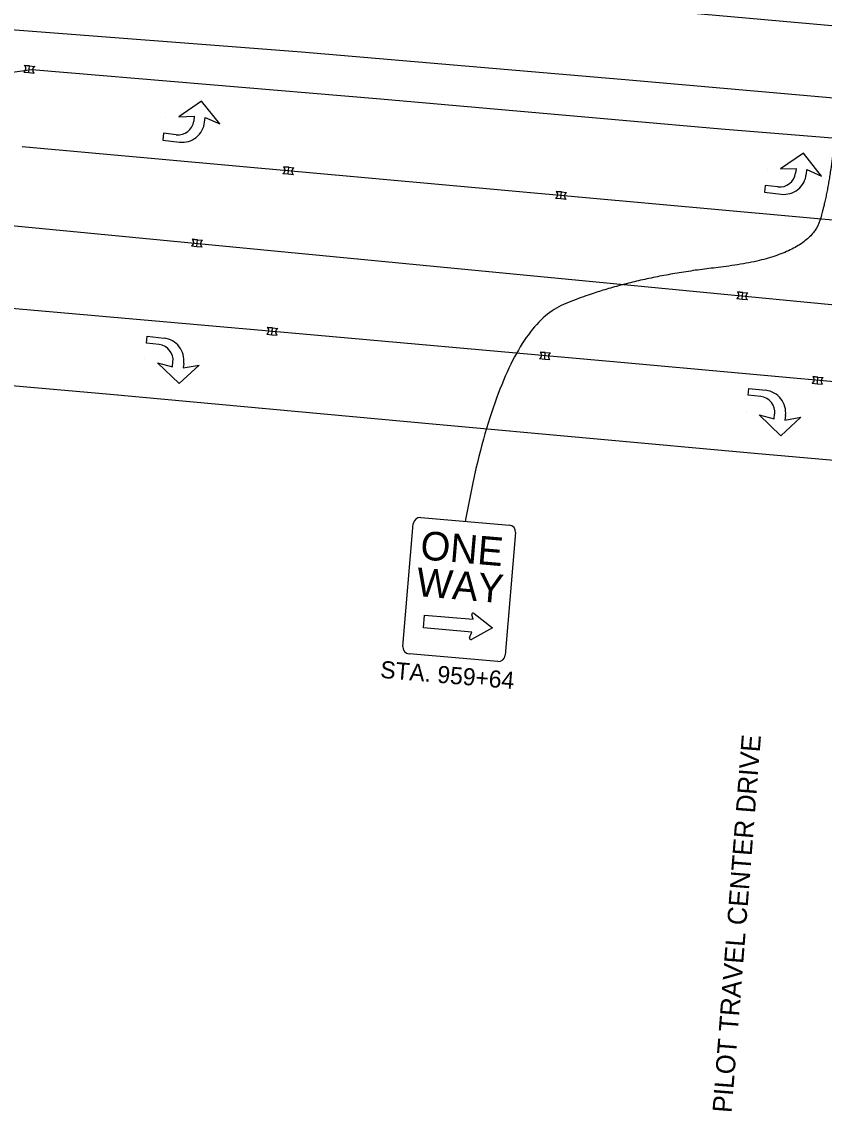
# Model space of a CAD drawing. Extents: x 1847379 to 1850904, y 217032 to 220169.
# Drawn here: x 1849979.4 to 1850096.6, y 218621.4 to 218780.5 of the extents above; entities that cross this region are included whole.
import ezdxf

# ---------------------------------------------------------------- set-up
doc = ezdxf.new("R2010")
doc.units = 0
for name, color, linetype in [('PM_P_Cells', 7, 'Continuous'), ('PM_P_Channelizing_Line', 7, 'Continuous'), ('PM_P_CL_Double_Solid', 7, 'Continuous'), ('PM_P_Edge_Line', 7, 'Continuous'), ('PM_P_Lane_Line', 7, 'Continuous'), ('SN_X_Public', 7, 'Continuous'), ('SN_X_Text', 7, 'Continuous')]:
    doc.layers.add(name, color=color, linetype=linetype)

msp = doc.modelspace()

# ---------------------------------------------------------------- linework, layer by layer
at = {"layer": 'PM_P_Cells'}
for p, q in [((1849980.55, 218774.09), (1849979.78, 218774.16)), ((1849979.78, 218774.16), (1849980.55, 218774.09)), ((1849980.46, 218773.11), (1849980.55, 218774.09)), ((1849980.55, 218774.09), (1849981.31, 218774.02)), ((1849979.69, 218773.18), (1849980.46, 218773.11)), ((1849979.69, 218773.18), (1849980.46, 218773.11)), ((1849980.46, 218773.11), (1849981.23, 218773.04)), ((1850005.68, 218768.96), (1850002.35, 218766.67)), ((1850008.34, 218765.62), (1850005.68, 218768.96)), ((1850000.4, 218766.57), (1850000.4, 218766.57)), ((1850002.35, 218766.67), (1850004.61, 218766.74)), ((1850004.61, 218766.74), (1850004.53, 218766.04)), ((1850006.12, 218765.88), (1850006.2, 218766.55)), ((1850006.2, 218766.55), (1850008.34, 218765.62)), ((1850000.12, 218764.25), (1850000, 218763.26)), ((1850001.97, 218764.03), (1850000.12, 218764.25)), ((1850008.34, 218765.62), (1850008.34, 218765.62)), ((1850000, 218763.26), (1850002.46, 218762.96)), ((1850093.59, 218761.35), (1850090.26, 218759.06)), ((1850096.25, 218758.01), (1850093.59, 218761.35)), ((1850018.41, 218759.28), (1850017.64, 218759.35)), ((1850017.64, 218759.35), (1850018.41, 218759.28)), ((1850017.55, 218758.38), (1850018.32, 218758.31)), ((1850017.55, 218758.38), (1850018.32, 218758.31)), ((1850018.32, 218758.31), (1850018.41, 218759.28)), ((1850018.32, 218758.31), (1850019.09, 218758.24)), ((1850018.41, 218759.28), (1850019.17, 218759.21)), ((1850088.31, 218758.96), (1850088.31, 218758.96)), ((1850090.26, 218759.06), (1850092.52, 218759.13)), ((1850092.52, 218759.13), (1850092.44, 218758.43)), ((1850094.03, 218758.28), (1850094.11, 218758.94)), ((1850094.11, 218758.94), (1850096.25, 218758.01)), ((1850096.25, 218758.01), (1850096.25, 218758.01)), ((1850088.03, 218756.64), (1850087.91, 218755.65)), ((1850089.88, 218756.42), (1850088.03, 218756.64)), ((1850057.39, 218754.77), (1850058.16, 218754.7)), ((1850057.39, 218754.77), (1850058.16, 218754.7)), ((1850058.25, 218755.68), (1850057.48, 218755.75)), ((1850057.48, 218755.75), (1850058.25, 218755.68)), ((1850058.16, 218754.7), (1850058.25, 218755.68)), ((1850058.16, 218754.7), (1850058.93, 218754.63)), ((1850058.25, 218755.68), (1850059.01, 218755.61)), ((1850087.91, 218755.65), (1850090.37, 218755.36)), ((1850005.07, 218748.7), (1850004.3, 218748.77)), ((1850004.3, 218748.77), (1850005.07, 218748.7)), ((1850004.98, 218747.73), (1850005.07, 218748.7)), ((1850005.07, 218748.7), (1850005.83, 218748.63)), ((1850004.21, 218747.79), (1850004.98, 218747.73)), ((1850004.21, 218747.79), (1850004.98, 218747.73)), ((1850004.98, 218747.73), (1850005.75, 218747.66)), ((1850084.73, 218741.01), (1850083.96, 218741.08)), ((1850083.96, 218741.08), (1850084.73, 218741.01)), ((1850084.64, 218740.04), (1850084.73, 218741.01)), ((1850084.73, 218741.01), (1850085.5, 218740.94)), ((1850083.87, 218740.11), (1850084.64, 218740.04)), ((1850083.87, 218740.11), (1850084.64, 218740.04)), ((1850084.64, 218740.04), (1850085.41, 218739.97)), ((1850016.05, 218735.81), (1850015.28, 218735.88)), ((1850015.28, 218735.88), (1850016.05, 218735.81)), ((1850015.96, 218734.83), (1850016.05, 218735.81)), ((1850016.05, 218735.81), (1850016.81, 218735.74)), ((1849997.62, 218733.61), (1849997.73, 218734.6)), ((1849997.73, 218734.6), (1850000.19, 218734.32)), ((1850015.19, 218734.9), (1850015.96, 218734.83)), ((1850015.19, 218734.9), (1850015.96, 218734.83)), ((1850015.96, 218734.83), (1850016.73, 218734.77)), ((1849999.47, 218733.39), (1849997.62, 218733.61)), ((1850055.89, 218732.23), (1850055.12, 218732.3)), ((1850055.12, 218732.3), (1850055.89, 218732.23)), ((1849997.35, 218731.29), (1849997.35, 218731.29)), ((1850002.41, 218727.69), (1849999.22, 218730.74)), ((1849999.22, 218730.74), (1850001.41, 218730.15)), ((1850001.41, 218730.15), (1850001.49, 218730.85)), ((1850055.03, 218731.33), (1850055.8, 218731.26)), ((1850055.03, 218731.33), (1850055.8, 218731.26)), ((1850055.8, 218731.26), (1850055.89, 218732.23)), ((1850055.8, 218731.26), (1850056.57, 218731.19)), ((1850055.89, 218732.23), (1850056.66, 218732.16)), ((1850005.3, 218730.38), (1850002.41, 218727.69)), ((1850003.07, 218730.63), (1850003, 218729.97)), ((1850003, 218729.97), (1850005.3, 218730.38)), ((1850005.3, 218730.38), (1850005.3, 218730.38)), ((1850094.87, 218727.74), (1850095.64, 218727.67)), ((1850094.87, 218727.74), (1850095.64, 218727.67)), ((1850095.73, 218728.64), (1850094.96, 218728.71)), ((1850094.96, 218728.71), (1850095.73, 218728.64)), ((1850095.64, 218727.67), (1850095.73, 218728.64)), ((1850095.64, 218727.67), (1850096.41, 218727.6)), ((1850095.73, 218728.64), (1850096.5, 218728.57)), ((1850085.53, 218726), (1850085.64, 218726.99)), ((1850087.38, 218725.78), (1850085.53, 218726)), ((1850085.64, 218726.99), (1850088.1, 218726.71)), ((1850085.26, 218723.68), (1850085.26, 218723.68)), ((1850090.32, 218720.08), (1850087.13, 218723.13)), ((1850087.13, 218723.13), (1850089.32, 218722.54)), ((1850089.32, 218722.54), (1850089.4, 218723.24)), ((1850093.21, 218722.77), (1850090.32, 218720.08)), ((1850090.98, 218723.02), (1850090.91, 218722.36)), ((1850090.91, 218722.36), (1850093.21, 218722.77)), ((1850093.21, 218722.77), (1850093.21, 218722.77))]:
    msp.add_line(p, q, dxfattribs=at)
for centre, radius, start, end in [((1849979.43, 218773.7), 0.576, 296.8063, 52.8586), ((1849979.43, 218773.7), 0.576, 296.8063, 52.8586), ((1849981.57, 218773.5), 0.576, 116.8063, 232.8586), ((1850002.24, 218766.31), 2.3, 263.1824, 353.1824), ((1850002.85, 218766.22), 3.28, 263.1824, 354.0909), ((1850017.29, 218758.89), 0.576, 296.8063, 52.8586), ((1850017.29, 218758.89), 0.576, 296.8063, 52.8586), ((1850019.43, 218758.7), 0.576, 116.8063, 232.8586), ((1850090.15, 218758.7), 2.3, 263.1824, 353.1824), ((1850090.76, 218758.61), 3.28, 263.1824, 354.0909), ((1850057.13, 218755.29), 0.576, 296.8063, 52.8586), ((1850057.13, 218755.29), 0.576, 296.8063, 52.8586), ((1850059.27, 218755.09), 0.576, 116.8063, 232.8586), ((1850003.95, 218748.31), 0.576, 296.8063, 52.8586), ((1850003.95, 218748.31), 0.576, 296.8063, 52.8586), ((1850006.09, 218748.12), 0.576, 116.8063, 232.8586), ((1850083.61, 218740.62), 0.576, 296.8063, 52.8586), ((1850083.61, 218740.62), 0.576, 296.8063, 52.8586), ((1850085.76, 218740.43), 0.576, 116.8063, 232.8586), ((1850014.93, 218735.42), 0.576, 296.8063, 52.8586), ((1850014.93, 218735.42), 0.576, 296.8063, 52.8586), ((1850017.07, 218735.22), 0.576, 116.8063, 232.8586), ((1849999.82, 218731.06), 3.28, 352.5446, 83.453), ((1849999.21, 218731.11), 2.3, 353.453, 83.453), ((1850054.77, 218731.84), 0.576, 296.8063, 52.8586), ((1850054.77, 218731.84), 0.576, 296.8063, 52.8586), ((1850056.92, 218731.65), 0.576, 116.8063, 232.8586), ((1850094.61, 218728.25), 0.576, 296.8063, 52.8586), ((1850094.61, 218728.25), 0.576, 296.8063, 52.8586), ((1850096.76, 218728.06), 0.576, 116.8063, 232.8586), ((1850087.73, 218723.45), 3.28, 352.5446, 83.453), ((1850087.12, 218723.5), 2.3, 353.453, 83.453)]:
    msp.add_arc(centre, radius, start, end, dxfattribs=at)
at = {"layer": 'PM_P_Channelizing_Line'}
for points in [[(1850652.98, 218698.12), (1850615.27, 218701.75), (1850564.66, 218706.78), (1850513.12, 218712.05), (1850461.3, 218717.14), (1850408.88, 218722.34), (1850360.86, 218727.03), (1850313.39, 218731.82), (1850265.8, 218736.37), (1849979.48, 218762.27)], [(1850650.65, 218674.09), (1850566.02, 218682.53), (1850518.02, 218687.39), (1850471.03, 218692.07), (1850419.06, 218697.16), (1850371.65, 218702.19), (1850311.6, 218707.75), (1850264.65, 218712.06), (1850215.84, 218717), (1850171.13, 218721.51), (1850121.19, 218725.85), (1850066.37, 218730.8), (1850014.99, 218735.41), (1849965.69, 218739.72), (1849914.21, 218744.36), (1849896.49, 218746.14)]]:
    msp.add_lwpolyline(points, dxfattribs=at)
at = {"layer": 'PM_P_CL_Double_Solid'}
msp.add_line((1849980.86, 218773.54), (1849932.52, 218766.94), dxfattribs=at)
at = {"layer": 'PM_P_Edge_Line'}
for p, q in [((1849965.29, 218780.39), (1850020.28, 218776.15)), ((1850020.28, 218776.15), (1850068.7, 218772.02)), ((1850031.82, 218769.24), (1849980.86, 218773.54)), ((1850068.7, 218772.02), (1850126.22, 218766.95)), ((1850081.59, 218764.87), (1850031.82, 218769.24)), ((1850132.45, 218760.65), (1850081.59, 218764.87))]:
    msp.add_line(p, q, dxfattribs=at)
msp.add_lwpolyline([(1849832.17, 218750.77), (1849894.17, 218734.94), (1849941.43, 218730.63), (1849992.34, 218726.14), (1850039.4, 218721.8), (1850086.44, 218717.54), (1850135.69, 218713.18), (1850171.07, 218709.94)], dxfattribs=at)
at = {"layer": 'PM_P_Lane_Line'}
msp.add_line((1849881.96, 218760.04), (1850650.78, 218685.87), dxfattribs=at)
msp.add_lwpolyline([(1849608.14, 218816.84), (1849659.46, 218813.21), (1849709.31, 218809.62), (1849760.21, 218805.9), (1849807.22, 218802.44), (1849857.63, 218799.12), (1849906.82, 218795.7), (1849957.46, 218791.82), (1850014.55, 218787.19), (1850067.13, 218782.71), (1850118.03, 218778.2), (1850167.47, 218773.95), (1850186.14, 218772.34)], dxfattribs=at)
at = {"layer": 'SN_X_Public'}
for p, q in [((1850035.08, 218689.28), (1850036.61, 218707.21)), ((1850037.69, 218708.12), (1850050.64, 218707.02)), ((1850051.55, 218705.94), (1850050.03, 218688.01)), ((1850045.5, 218694.12), (1850048.17, 218692.01)), ((1850038.1, 218692), (1850038.26, 218693.87)), ((1850038.26, 218693.87), (1850045.34, 218693.27)), ((1850045.34, 218693.26), (1850045.17, 218693.91)), ((1850045.16, 218691.4), (1850038.1, 218692)), ((1850044.82, 218690.58), (1850045.16, 218691.4)), ((1850048.17, 218692.01), (1850045.11, 218690.32)), ((1850048.95, 218687.1), (1850036, 218688.2))]:
    msp.add_line(p, q, dxfattribs=at)
for centre, radius, start, end in [((1850037.6, 218707.13), 1, 85.1482, 175.1482), ((1850050.56, 218706.03), 1, 355.1482, 85.1482), ((1850045.37, 218693.96), 0.208, 51.5722, 194.2116), ((1850045.01, 218690.5), 0.208, 157.2248, 298.8737), ((1850036.08, 218689.19), 1, 175.1482, 265.1482), ((1850049.03, 218688.09), 1, 265.1482, 355.1482)]:
    msp.add_arc(centre, radius, start, end, dxfattribs=at)
at = {"layer": 'SN_X_Text'}
msp.add_open_spline([(1850098.38, 218766.24), (1850097.65, 218756.86), (1850094.34, 218746.14), (1850067.97, 218743.17), (1850049.26, 218735.39), (1850044.16, 218707.57)], degree=2, dxfattribs=at)

# ---------------------------------------------------------------- texts
at = {"layer": 'SN_X_Public'}
for s, height, rotation, p in [('ONE', 4.172, 355.1482, (1850037.52, 218702.04)), ('WAY', 4.172, 355.1482, (1850036.93, 218696.68)), ('PILOT TRAVEL CENTER DRIVE', 2.8, 85.5355, (1850083.1, 218621.11))]:
    msp.add_text(s, height=height, rotation=rotation, dxfattribs=at).set_placement(p)
at = {"layer": 'SN_X_Text'}
msp.add_text('STA. 959+64', height=2.5, rotation=355.1482, dxfattribs=at).set_placement((1850031.71, 218684.72))

doc.saveas('drawing.dxf')
